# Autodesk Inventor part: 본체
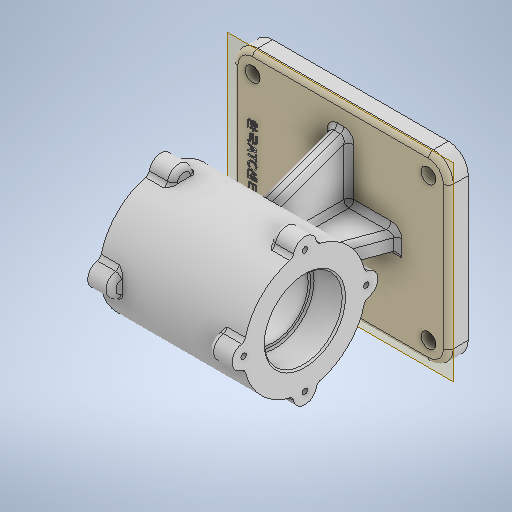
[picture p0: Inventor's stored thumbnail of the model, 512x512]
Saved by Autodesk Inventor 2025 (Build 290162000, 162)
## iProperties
Created: 2025-08
Part Number: 본체
Material: 일반
Document SubType Name: Modeling
Designer: infra02
Density: 1 g/cm^3
Appearance: 기본값
Author: infra02
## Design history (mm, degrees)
sketch "스케치1"
  geometry: L1 (65, -55)-(-65, -55); L2 (-65, -55)-(-65, 55); L3 (-65, 55)-(65, 55); L4 (65, 55)-(65, -55); L5 (65, -55)-(-65, 55); L6 (-65, -55)-(65, 55); 1 further point
  constraints: 12 end point, 2 midpoint, 2 parallel, 1 horizontal, 1 perpendicular
  dimensions: "d0" = 130 distance of L2.end L3.end; "d1" = 110 distance of L1.end L2.end
extrude "돌출1" new body sketch "스케치1" distance "d2" = 12; taper "d3" = 0 deg
sketch "스케치3"
  geometry: L1 (38.5, 119)-(-48.5, 119); L2 (-48.5, 119)-(-48.5, 82); L3 (-48.5, 82)-(38.5, 82); L4 (38.5, 82)-(38.5, 119); L5 (38.5, 105.5)-(19.5, 105.5); L6 (19.5, 105.5)-(19.5, 82); L7 (19.5, 82)-(38.5, 82); L8 (38.5, 82)-(38.5, 105.5); L9 (19.5, 103)-(-29.5, 103); L10 (-29.5, 103)-(-29.5, 82); L11 (-29.5, 82)-(19.5, 82); L12 (19.5, 82)-(19.5, 103); L13 (-29.5, 103)-(-29.5, 105.5); L14 (-29.5, 105.5)-(-48.5, 105.5); L15 (65, 0)-(65, 12) reference; L16 (65, 0)-(-65, 0) reference; 2 further points
  constraints: 28 end point, 6 parallel, 5 point on line, 4 perpendicular, 3 horizontal, 1 midpoint, 1 vertical
  dimensions: "d6" = 19 distance between parallel lines of L6 L4; "d7" = 19 distance between parallel lines of L2 L10; "d8" = 87 distance between parallel lines of L2 L4; "d9" = 23.5 distance between parallel lines of L5 L3; "d10" = 21 distance between parallel lines of L9 L11; "d11" = 23.5 distance between parallel lines of L14 L3 (= d9); "d12" = 70 distance from line of point (-5, 82) L15; "d13" = 82 distance between parallel lines of L11 L16; "d14" = 37 distance between parallel lines of L1 L11
revolve "회전1" sketch "스케치3" stored, may be unused: angle "d15" = 90 deg
sketch "스케치4"
  geometry: L1 (0, 0)-(37, 0); C1 r 7 at (37, 0); C2 r 7 at (0, 37); C3 r 7 at (-37, 0); C4 r 7 at (0, -37); A1 r 37 centre (0, 0) between (37, 0) and (0, 37) reference; 1 further point
  constraints: 4 centre point, 2 end point, 2 point on circle, 2 vertical alignment, 1 coincident, 1 horizontal, 9 other
  dimensions: "d16" = 14 diameter of C1; "d19" = 360 deg dimension on L1.start C1.centre (derived); "d21" = 0 distance from line of A1.centre L1
  node "스케치 - 원형 패턴1" dims "d19" = 360 deg (derived)
extrude "돌출2" join sketch "스케치4" distance "d22" = 14; taper "d23" = 0 deg
hole "구멍1" sketch "스케치4" diameter "d24" = 3.242; stored, may be unused: countersink angle "d28" = 90 deg, drill point angle "d30" = 118 deg; dims "d25" = 8, "d26" = 4, "d27" = 2, "d29" = 10
node "작업 평면1"
sketch "스케치6"
  geometry: C1 r 7 at (-37, 37) reference; C2 r 7 at (-74, 0) reference; C3 r 7 at (0, 0) reference; C4 r 1.621 at (-37, -37) reference; C5 r 1.621 at (0, 0) reference; C6 r 1.621 at (-37, 37) reference; C7 r 1.621 at (-74, 0) reference; A1 r 7 centre (-37, -37) between (-43.969, -36.338) and (-30.031, -36.338) reference; A2 r 7 centre (-37, -37) between (-43.969, -36.338) and (-30.031, -36.338) reference; 1 further point
extrude "돌출3" join sketch "스케치6" distance "d32" = 14; taper "d33" = 0 deg
hole "구멍2" sketch "스케치6" diameter "d34" = 3.242; stored, may be unused: countersink angle "d38" = 90 deg, drill point angle "d40" = 118 deg; dims "d35" = 8, "d36" = 4, "d37" = 2, "d39" = 10
sketch "스케치9"
  geometry: L1 (-34.5, 45)-(24.5, 45) reference; L2 (13.263, 45)-(25.274, 12); L3 (65, 12)-(-65, 12) reference; L4 (-22.032, 46.877)-(-34.726, 12); 3 further points
  constraints: 4 end point, 2 point on line
  dimensions: "d43" = 110 deg angle of L2 L3; "d44" = 110 deg angle of L3 L4; "d45" = 60 distance of L4.end L2.end
extrude "돌출4" join sketch "스케치9" stored distance "d46" = 10; taper "d47" = 0 deg
sketch "스케치10"
  geometry: L1 (25.336, 55.036)-(41, 12); L2 (55, 12)-(-55, 12) reference; L3 (-25.336, 55.036)-(-41, 12); A1 r 37 centre (0, 82) between (6.969, 45.662) and (36.338, 75.031) reference; A2 r 37 centre (0, 82) between (-36.338, 75.031) and (-6.969, 45.662) reference; 1 further point
  constraints: 4 end point, 2 point on circle, 2 point on line
  dimensions: "d48" = 110 deg angle of L1 L2; "d49" = 110 deg angle of L2 L3; "d50" = 14 distance of L1.end L2.start; "d51" = 14 distance of L2.end L3.end
feature "리브1" dims "d52" = 1, "d53" = 10, "d54" = 0, "d55" = 0, "d56" = 1, "d57" = 1
feature "리브2" dims "d58" = 1, "d59" = 10, "d60" = 0, "d61" = 0, "d62" = 1, "d63" = 1
sketch "스케치11"
  geometry: L1 (53, 43)-(-53, 43); L2 (-53, 43)-(-53, -43); L3 (-53, -43)-(53, -43); L4 (53, -43)-(53, 43); L5 (-65, 55)-(-65, -55) reference; L6 (-65, -55)-(65, -55) reference; L7 (65, 55)-(-65, 55) reference; 5 further points
  constraints: 8 end point, 4 coincident, 2 parallel, 1 horizontal, 1 perpendicular
  dimensions: "d64" = 12 distance between parallel lines of L2 L5; "d65" = 106 distance of L2.end L3.end; "d66" = 86 distance of L3.end L1.start; "d67" = 12 distance between parallel lines of L6 L3; "d68" = 110 distance between parallel lines of L6 L7 (derived)
hole "구멍3" sketch "스케치11" at (53, 43), (53, -43), (-53, 43), (-53, -43) diameter "d69" = 9; stored, may be unused: countersink angle "d73" = 90 deg, drill point angle "d75" = 118 deg; dims "d70" = 8, "d71" = 4, "d72" = 2, "d74" = 10
fillet "모깎기1" dims "d76" = 12
chamfer "모따기1" distance "d77" = 1; stored, may be unused: second distance "d78" = 2, angle "d79" = 45 deg
chamfer "모따기2" distance "d80" = 1; stored, may be unused: second distance "d81" = 2, angle "d82" = 45 deg
fillet "모깎기2" dims "d83" = 1
fillet "모깎기3" dims "d84" = 3
fillet "모깎기4" dims "d85" = 3
fillet "모깎기5" dims "d86" = 3
fillet "모깎기6" dims "d87" = 3
node "작업 평면2"
sketch "스케치14"
  geometry: L1 (-55.829, 19.887)-(-55.829, -19.887); L2 (-55.829, -19.887)-(-50.171, -19.887); L3 (-50.171, -19.887)-(-50.171, 19.887); L4 (-50.171, 19.887)-(-55.829, 19.887); L5 (-65, 43)-(-65, -43) reference; L6 (5, 66.257)-(5, -70.664); 5 further points
  constraints: 3 midpoint, 2 end point, 1 horizontal alignment, 1 vertical, 1 vertical alignment, 2 other
  dimensions: "d89" = 70 distance between parallel lines of L6 L5; "d90" = 58 distance from line of L6 point (-53, 19.887) (derived)
feature "엠보싱1" sketch "스케치14" dims "d0" = 130, "d1" = 110, "d10" = 21, "d91" = 0.5, "d92" = 0
node "솔리드1"
feature "A9D066F2-1C7D-4E18-AEED-F7BC21143FA4" dims "d69" = 9, "d70" = 8, "d71" = 4, "d72" = 2, "d73" = 90 deg, "d74" = 10, "d75" = 118 deg
other parameters: "d31" = -87, "d88" = 0
